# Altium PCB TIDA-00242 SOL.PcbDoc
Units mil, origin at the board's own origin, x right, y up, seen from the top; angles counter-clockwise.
Board outline 2500 x 1000 mil, 2 copper layers (Top Layer, Bottom Layer), stack 62 mil thick; 20 components, 6 nets, 29 pads, 0 vias.
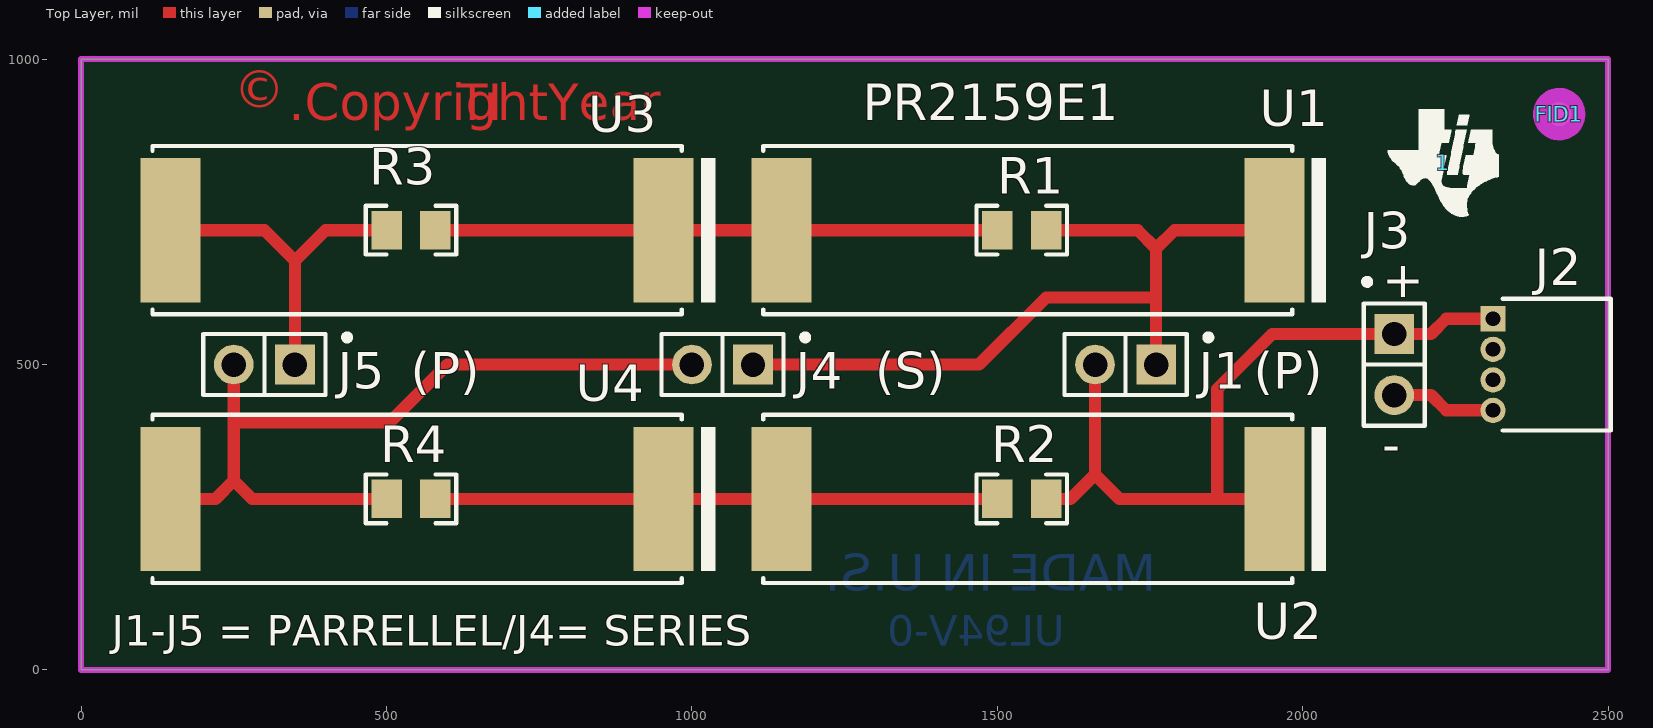
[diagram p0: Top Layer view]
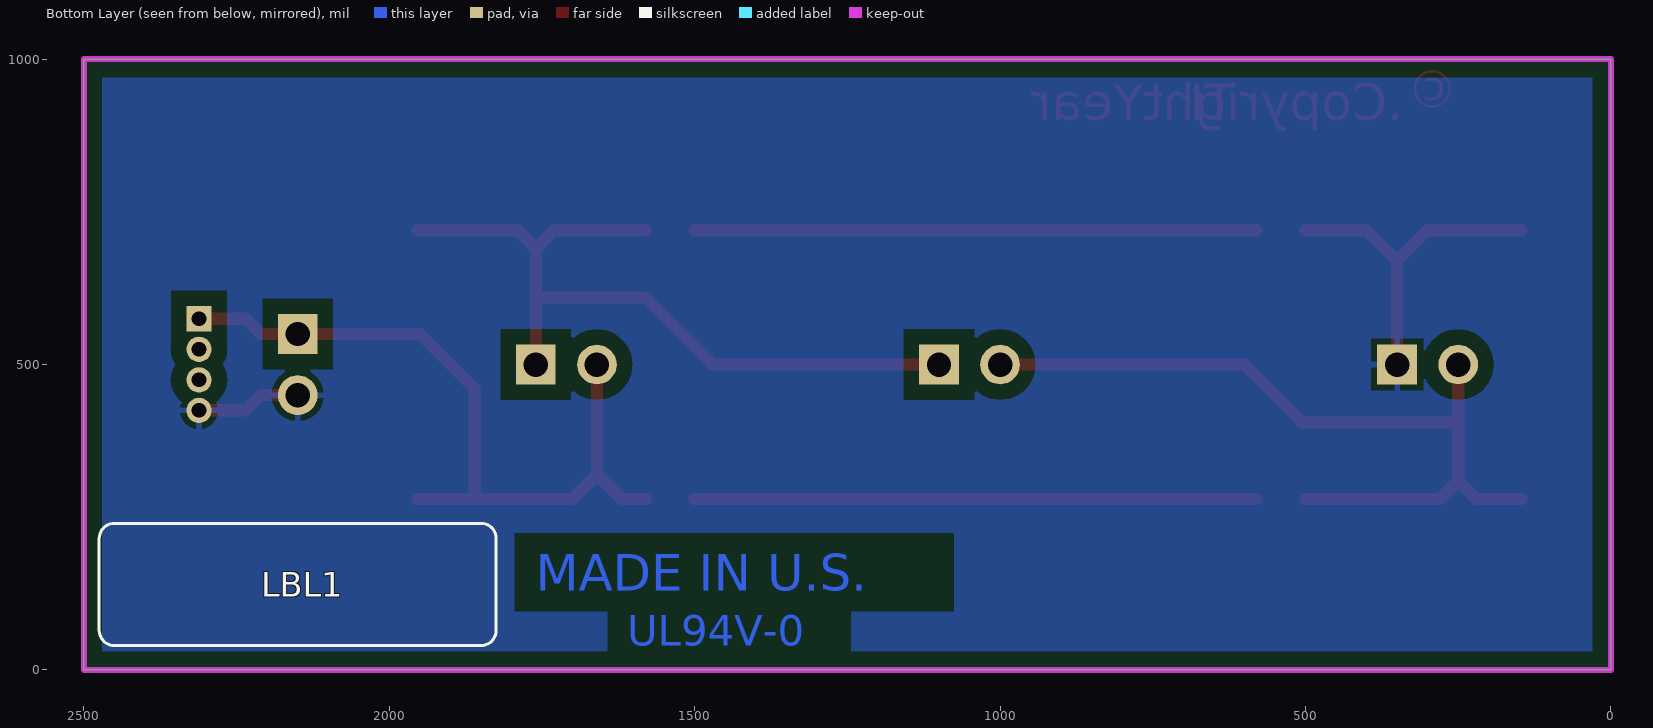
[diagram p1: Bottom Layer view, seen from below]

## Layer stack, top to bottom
Top Layer: signal copper 1.4
Dielectric: core 59.2, FR-4, Dk 4.8
Bottom Layer: signal copper 1.4

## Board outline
0,0 0,1000 2500,1000 2500,0 0,0

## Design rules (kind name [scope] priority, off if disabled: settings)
AcuteAngle [All] p1: minimum=4.50000000000000E+0001 checktracksonly=FALSE
AssemblyTestPointUsage [All] p1: valid=2
Clearance Clearance_BoardEdge_MountingHoles [OnCopper and InComponentClass('Mounting Holes') vs IsKeepOut] p1: gap=40
Clearance Clearance_BoardEdge_Poly [OnCopper and InPoly vs IsKeepOut] p2: gap=25
Clearance Clearance_BoardEdge [OnCopper and Not InComponentClass('Logo') and not InComponentClass('FiducialMark') and not InRegion(1000,500,4000,800) and Not IsKeepout vs IsKeepOut] p3: gap=75
Clearance Clearance_Poly [InPolygon] p4: gap=25
Clearance [All] p5: gap=8
ComponentClearance ComponentClearance_Logo [InComponentClass('Logo')] p1: gap=50 collisioncheckmode=3 verticalgap=10 showdistances=FALSE
ComponentClearance ComponentClearance_ScrewToNut [(HasFootprint('NY PMS 440 0025 PH')) vs (HasFootprint('Keystone_1902C'))] p2: gap=20 collisioncheckmode=3 verticalgap=10 showdistances=FALSE
ComponentClearance ComponentClearance_MountingHoles [InComponentClass('Mounting Holes')] p3: gap=20 collisioncheckmode=3 verticalgap=100000 showdistances=FALSE
ComponentClearance ComponentClearance_SmallPassives [HasFootprint('0201*') or HasFootprint('0402*') or HasFootprint('0508') or HasFootprint('0603*') or HasFootprint('0612') or HasFootprint('0805*') or HasFootprint('0815*') or HasFootprint('0830*') or HasFootprint('1206*') or HasFootprint('1210*') or HasFootprint('1808*') or HasFootprint('1812*') or HasFootprint('1825*') or HasFootprint('2010*') or HasFootprint('2220*') or HasFootprint('2225*') or HasFootprint('2512*') or HasFootprint('2728*') or HasFootprint('3518*') vs HasFootprint('0201*') or HasFootprint('0402*') or HasFootprint('0508') or HasFootprint('0603*') or HasFootprint('0612') or HasFootprint('0805*') or HasFootprint('0815*') or HasFootprint('0830*') or HasFootprint('1206*') or HasFootprint('1210*') or HasFootprint('1808*') or HasFootprint('1812*') or HasFootprint('1825*') or HasFootprint('2010*') or HasFootprint('2220*') or HasFootprint('2225*') or HasFootprint('2512*') or HasFootprint('2728*') or HasFootprint('3518*')] p4: gap=20 collisioncheckmode=3 verticalgap=10 showdistances=FALSE
ComponentClearance ComponentClearance_THtoSMT [IsThruComponent vs IsSMTComponent] p5: gap=20 collisioncheckmode=3 verticalgap=20 showdistances=FALSE
ComponentClearance ComponentClearance_THtoTH [IsThruComponent vs IsThruComponent] p6: gap=20 collisioncheckmode=3 verticalgap=20 showdistances=FALSE
ComponentClearance [All] p7: gap=20 collisioncheckmode=3 verticalgap=20 showdistances=FALSE
DiffPairsRouting [All] p1: maxlimit=100 minlimit=10 mostfreqgap=10 maxuncoupledlength=1000
FabricationTestPointUsage TestPointUsage [All] p1: valid=2 allowmultiple=FALSE
FabricationTestpoint Testpoint [All] p1: side=3 testpointundercomponent=TRUE minsize=40 maxsize=100 preferedsize=60 minholesize=0 maxholesize=40 preferedholesize=32 testpointgrid=1 allowsidetop=TRUE allowsidebottom=TRUE usegrid=TRUE gridtolerance=0.01
FanoutControl Fanout_LCC [IsLCC] p1: bgadir=Out bgaviamode=Centered fanoutstyle=Auto fanoutdirection=Alternating viagrid=1 // Fanout_LCC (Default Rule)
FanoutControl Fanout_BGA [IsBGA] p2: bgadir=Out bgaviamode=Centered fanoutstyle=Auto fanoutdirection=Alternating viagrid=1 // Fanout_BGA (Default Rule)
FanoutControl Fanout_Default [All] p4: bgadir=Out bgaviamode=Centered fanoutstyle=Auto fanoutdirection=Alternating viagrid=1 // Fanout_Default (Default Rule)
FanoutControl Fanout_Small [(CompPinCount < 5)] p5: bgadir=Out bgaviamode=Centered fanoutstyle=Auto fanoutdirection=OutThenIn viagrid=1 // Fanout_Small (Default Rule)
HoleSize [All] p1: absolutevalues=TRUE maxlimit=251 minlimit=8 maxpercent=80.000 minpercent=20.000
MinimumAnnularRing [All] p1: minimumring=9
MinimumSolderMaskSliver MinimumSolderMaskSliver_Logo [InComponentClass('Logo') vs InComponentClass('Logo')] p1: minsoldermaskwidth=0.7
MinimumSolderMaskSliver [All] p2: minsoldermaskwidth=4
PlaneConnect [All] p1: planeconnectstyle=Relief reliefexpansion=10 reliefentries=4 reliefconductorwidth=10 reliefairgap=10
PolygonConnect [All] p1: connectstyle=Relief reliefconductorwidth=10 reliefentries=4 polygonreliefangle="90 Angle" airgapwidth=10
RoutingVias [All] p1: holewidth=16 width=34 viastyle="Through Hole" minholewidth=8 minwidth=26 maxholewidth=40 maxwidth=65
SMDToCorner [All] p1: distance=30000
SilkToSilkClearance [All] p1: silktosilkclearance=5
SilkscreenOverComponentPads [All] p1: minsilkscreentomaskgap=5
SolderMaskExpansion [All] p1: expansion=3
Width [All] p1: maxlimit=100 minlimit=6 preferedwidth=10 checkconnectedcopper=TRUE
14 further rules are at their usual default settings.

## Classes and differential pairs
component class "PR2159 sheet 2": J1 J2 J3 J4 J5 R1 R2 R3 R4 U1 U2 U3 U4
component class Logo: ""
component class "PR2159 sheet 3": FID1 LBL1 ZZ1 ZZ2 ZZ3 ZZ4 ""
component class FiducialMark: FID1
component class AssemblyNote: ZZ1 ZZ2 ZZ3 ZZ4
component class Label: LBL1

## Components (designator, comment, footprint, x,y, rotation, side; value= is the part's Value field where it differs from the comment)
1 "Texas Instruments" TI_Symbol_Overlay_Small 2230,830 r0 top
FID1 "Fiducial" Fiducial10-20 2420,910 r0 top
J1 "90120-0122" CONN_90120-0122 1710,500 r180 top
J2 "LPPB041NGCN-RC" Sullins_LPPB041NGCN 2410,500 r90 top
J3 "90120-0122" CONN_90120-0122 2150,500 r270 top
J4 "90120-0122" CONN_90120-0122 1050,500 r180 top
J5 "90120-0122" CONN_90120-0122 300,500 r180 top
LBL1 "Size: 0.65\" x 0.20 \"" Label_650x200 2150,140 r180 bottom
R1 "CRCW08050000Z0EA" 0805_HV 1540,720 r0 top
R2 "CRCW08050000Z0EA" 0805_HV 1540,280 r0 top
R3 "CRCW08050000Z0EA" 0805_HV 540,720 r0 top
R4 "CRCW08050000Z0EA" 0805_HV 540,280 r0 top
U1 "KXOB22-04X3L" KXOB22-04X3 1550,720 r180 top
U2 "KXOB22-04X3L" KXOB22-04X3 1550,280 r180 top
U3 "KXOB22-04X3L" KXOB22-04X3 550,720 r180 top
U4 "KXOB22-04X3L" KXOB22-04X3 550,280 r180 top
ZZ1 "This Assembly Note is for PCB labels only" AssemblyNoteLabel 185,3938 r0 top
ZZ2 "These assemblies are ESD sensitive, ESD precautions shall be observed." AssemblyNote 185,3829.11 r0 top
ZZ3 "These assemblies must be clean and free from flux and all contaminants. Use of no clean flux is not acceptable." AssemblyNote 185,3740.56 r0 top
ZZ4 "These assemblies must comply with workmanship standards IPC-A-610 Class 2., unless otherwise specified." AssemblyNote 185,3652 r0 top

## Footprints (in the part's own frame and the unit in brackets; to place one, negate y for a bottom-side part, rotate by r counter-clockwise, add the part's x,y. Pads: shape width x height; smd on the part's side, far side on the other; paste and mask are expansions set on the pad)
0805_HV [mil] "0805 with 30mil clearance between pads"
  rect 50x63 smd: 1(-40,0) 2(40,0)
  silkscreen extent -74,-40 74,40, body extent -43,-29 43,29, height 43
AssemblyNote [mil] "Assembly Note"
AssemblyNoteLabel [mil] "Assembly Note for PCB Labels"
CONN_90120-0122 [mm] "Molex"
  rect 1.65x1.65 hole 1.016 mask+0: 1(-1.27,0)
  round 1.65 hole 1.016 mask+0: 2(1.27,0)
  silkscreen extent -3.57,-1.27 2.54,1.27, body extent -2.54,-1.27 2.54,1.27, height 9.29
Fiducial10-20 [mm]
  round 1 smd paste-0.5 mask+0.5: 1(0,0)
  Top Layer keep-out circle w1.178: c0,0 r0.5
KXOB22-04X3 [mm] "IXYS"
  rect 2.5x6 smd: 1(-10.25,0) 2(10.25,0)
  silkscreen extent -12.4,-3.5 11,3.5, body extent -11,-3.5 11,3.5, height 1.81
Label_650x200 [mil] "Thermal Transfer Label"
  silkscreen extent -325,-100 325,100, body extent -326,-101 326,101, height 1
Sullins_LPPB041NGCN [mm] "Sullins"
  rect 1.05x1.05 hole 0.61 mask+0.05: 1(1.905,2.5)
  round 1.05 hole 0.61 mask+0.05: 2(0.635,2.5) 3(-0.635,2.5) 4(-1.905,2.5)
  silkscreen extent -2.74,-2.4 2.74,2.1, body extent -2.74,-2.4 2.74,2.58, height 2.22
TI_Symbol_Overlay_Small [mil]
  silkscreen extent -90,-88 91,88

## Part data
1: library part TI_Logo, "Texas Instrument Corporate Signature"
FID1: "Fiducial mark.  There is nothing to buy or mount."
J1 J3 J4 J5: "Header, 100mil, 2x1, Tin plated, TH"
J2: "Receptacle, 50mil, 4x1, R/A, TH"
LBL1: library part THT-14-423-10, "Thermal Transfer Printable Labels, 0.650\" W x 0.200\" H - 10,000 per roll"
R1 R2 R3 R4: "RES, 0 ohm, 5%, 0.125W, 0805"
U1 U2 U3 U4: "MONOCRYSTALLINE SOLAR CELL, 22MM X 7MM, SMD"
ZZ1: library part AssemblyNoteLabel
ZZ2 ZZ3 ZZ4: library part AssemblyNote

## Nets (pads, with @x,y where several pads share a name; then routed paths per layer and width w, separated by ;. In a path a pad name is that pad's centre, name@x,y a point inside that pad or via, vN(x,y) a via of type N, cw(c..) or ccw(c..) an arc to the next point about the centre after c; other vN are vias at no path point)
GND: J2.4 J3.2 J5.1 R3.1 U3.2 | length 736.9
  Top Layer w20: U3.2 300,720 350,670 ; J5.1 350,670 ; R3.1 400,720 350,670 ; J3.2 2210,450 2235,425 J2.4
NetJ1_1: J1.1 J4.1 R1.2 U1.1 | length 1294
  Top Layer w20: J4.1 1470,500 1580,610 1760,610 ; R1.2 1730,720 1760,690 ; J1.1 1760,610 ; U1.1 1790,720 1760,690 ; 1760,610 1760,690
NetJ1_2: J1.2 J2.1 J3.1 R2.2 U2.1 | length 1265.9
  Top Layer w20: R2.2 1620,280 1660,320 ; J1.2 1660,320 ; U2.1 1860,280 ; J2.1 2235,575 2210,550 J3.1 1950,550 1860,460 1860,280 ; 1660,320 1700,280 1860,280
NetJ4_2: J4.2 J5.2 R4.1 U4.2 | length 1357.7
  Top Layer w20: U4.2 220,280 250,310 ; J5.2 250,405 ; R4.1 280,280 250,310 ; J4.2 600,500 505,405 250,405 ; 250,310 250,405
NetR1_1: R1.1 R3.2 U1.2 U3.1 | length 920
  Top Layer w20: R3.2 U3.1 U1.2 R1.1
NetR2_1: R2.1 R4.2 U2.2 U4.1 | length 920
  Top Layer w20: R4.2 U4.1 U2.2 R2.1
pads on no net: FID1.1 J2.2 J2.3

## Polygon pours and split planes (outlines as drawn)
GND on Bottom Layer "Bottom Layer-No Net" (solid, remove dead copper, pour order 4): 0,0 0,1000 2500,1000 2500,0 0,0

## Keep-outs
Keep-Out Layer:
  lines w10: 4950,-5 ccw(c4950,0) 4955,0 ; 4950,-5 ccw(c4950,0) 4955,0 ; 4950,-5 ccw(c4950,0) 4955,0 ; 4950,-5 ccw(c4950,0) 4955,0 ; 4950,-5 ccw(c4950,0) 4955,0 ; 4950,-5 ccw(c4950,0) 4955,0 ; 4950,3455 cw(c4950,3450) 4955,3450 ; 4950,3455 cw(c4950,3450) 4955,3450 ; 4950,3455 cw(c4950,3450) 4955,3450 ; 4950,3455 cw(c4950,3450) 4955,3450 ; 4950,3455 cw(c4950,3450) 4955,3450 ; 4950,3455 cw(c4950,3450) 4955,3450 ; 0,0 2500,0 2500,1000 0,1000 0,0
  text ".Layer_Name" at 577,-858.49 h60

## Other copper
Top Layer:
  text "©" at 250,900 h105
  text ".CopyrightYear" at 340,900 h60
  text "TI" at 616,900 h60
  text ".Layer_Name" at 577,-858.49 h60
Bottom Layer:
  text ".VersionControl_RevNumber" at 3891,179.5 h60
  text "SVN:" at 4170,179.5 h60
  text "MADE IN U.S." at 1760,130 h60
  text "UL94V-0" at 1610,40 h50
  text ".Layer_Name" at 577,-858.49 h60

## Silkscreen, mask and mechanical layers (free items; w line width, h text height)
Top Overlay:
  text "PR2159E1" at 1280,900 h60
  text "+" at 2130,610 h60
  text "(P)" at 540,460 h60
  text "(S)" at 1300,460 h60
  text "(P)" at 1920,460 h60
  text "-" at 2130,340 h60
  text "J1-J5 = PARRELLEL/J4= SERIES" at 50,40 h50
  text ".Layer_Name" at 577,-858.49 h60
Bottom Overlay:
  text ".Layer_Name" at 577,-858.49 h60
Top Paste:
  text ".Layer_Name" at 577,-858.49 h60
Bottom Paste:
  text ".Layer_Name" at 577,-858.49 h60
Top Solder:
  text ".Layer_Name" at 577,-858.49 h60
  text ".Layer_Name" at 577,-858.49 h60
Bottom Solder:
  text ".Layer_Name" at 577,-858.49 h60
Drill Guide:
  text ".Layer_Name" at 577,-858.49 h60
M1 Board Outline:
  lines w10: 750,1000 0,1000 ; 0,1000 0,0 2500,0 2500,1000 0,1000
  text ".Layer_Name" at 577,-858.49 h60
M2 Board Dimensions:
  rectangle: -0.5,-285.5 124.5,-160.5
  rectangle: 124.5,-410.5 499.5,-285.5
  lines w7: -0.5,-285.5 999.5,-285.5 ; 124.5,-410.5 124.5,-160.5 ; 249.5,-410.5 249.5,-160.5 ; 499.5,-410.5 499.5,-160.5 ; 749.5,-410.5 749.5,-160.5 ; -0.5,-410.5 999.5,-410.5 999.5,-160.5 -0.5,-160.5 -0.5,-410.5
  lines w10: -0.5,-475.5 -0.5,-455.5 ; 59.5,-485.5 -0.5,-465.5 ; 59.5,-445.5 -0.5,-465.5 ; 223.58,-465.5 -0.5,-465.5 ; 775.42,-465.5 999.5,-465.5 ; 939.5,-485.5 999.5,-465.5 ; 939.5,-445.5 999.5,-465.5 ; 999.5,-475.5 999.5,-455.5
  text "1000 (mil)" at 233.58,-501.49 h60
  text ".Layer_Name" at 577,-858.49 h60
M3 3D STEP Top:
  text ".Layer_Name" at 577,-858.49 h60
M4 3D STEP Bottom:
  text ".Layer_Name" at 577,-858.49 h60
M5 Assembly Top:
  lines w7: 5139,110.5 6264,110.5 ; 5139,233 6261.5,233 ; 5454,-9.5 5454,353 ; 5839,-9.5 5139,-9.5 ; 5839,353 5139,353 ; 5139,-9.5 6264,-9.5 6264,353 5139,353 ; 5139,-9.5 5139,353
  lines w10: -292,-930.17 6308,-930.17 ; -292,-726.83 6310,-726.83 ; -292,-523.5 -292,-1133.5 3713,-1133.5 6310,-1133.5 6310,-523.5 -291.5,-523.5 -291.5,-1133.5 1284,-1133.5 ; 2173,-1133.5 2173,-523.5 ; 3440,-726.83 3440,-523.5 ; 4280,-726.83 4280,-523.5 ; 4902,-1140 4902,-937.17
  text "TABLE 1" at 5526.5,388 h40
  text "Variant" at 5164,278 h40
  text "Label text" at 5599,278 h40
  text "001" at 5231.5,158 h40
  text "ChangeMe!" at 5509,155.5 h40
  text "002" at 5231.5,33 h40
  text "ChangeMe!" at 5504,30.5 h40
  text "COMPONENTS MARKED 'DNP' SHOULD NOT BE POPULATED." at 1153.5,-318.5 h60
  text "ASSEMBLY VARIANT:" at 1153,-434 h60
  text ".VariantName" at 2189,-434 h60
  text "PCB VIEWED FROM TOP SIDE" at -228.5,-655.67 h60
  text "BOARD #:" at 2248,-655.67 h60
  text ".PRJ_Number" at 2793.5,-655.67 h60
  text "REV:" at 3638,-655.67 h60
  text ".PCB_Rev" at 3929.5,-655.67 h60
  text "SVN REV:" at 4476,-655.67 h60
  text ".VersionControl_RevNumber" at 4982,-655.67 h60
  text "IGNORE ->" at -228.5,-858.49 h60
  text "PLOT NAME =" at -228.5,-1064.34 h60
  text ".plot_File_Name" at 577,-1064.34 h60
  text "GENERATED    :" at 2250,-1064.34 h60
  text ".Print_Date" at 3119.5,-1064.34 h60
  text ".Print_Time" at 3848.5,-1064.34 h60
  text "TEXAS INSTRUMENTS" at 5113,-1064.34 h60
M6 Assembly Bottom:
  lines w10: -292.5,-727.33 6309.5,-727.33 ; -290.5,-930.67 6309.5,-930.67 ; 1115.5,-1140.5 1115.5,-937.67 ; 1737.5,-727.33 1737.5,-524 ; 2577.5,-727.33 2577.5,-524 ; 3844.5,-1134 3844.5,-524 ; 4733.5,-1134 6309,-1134 6309,-524 -292.5,-524 -292.5,-1134 2304.5,-1134 6309.5,-1134 6309.5,-524
  text "COMPONENTS MARKED 'DNP' SHOULD NOT BE POPULATED." at 6102,-318 h60
  text ".VariantName" at 5058,-434 h60
  text "ASSEMBLY VARIANT:" at 6097,-434 h60
  text ".VersionControl_RevNumber" at 1035.5,-656.17 h60
  text "SVN REV:" at 1541.5,-656.17 h60
  text ".PCB_Rev" at 2088,-656.17 h60
  text "REV:" at 2379.5,-656.17 h60
  text ".PRJ_Number" at 3224,-656.17 h60
  text "BOARD #:" at 3769.5,-656.17 h60
  text "PCB VIEWED FROM BOTTOM SIDE" at 6246,-656.17 h60
  text "IGNORE ->" at 2547.85,-858.49 h60
  text "TEXAS INSTRUMENTS" at 904.5,-1064.84 h60
  text ".Print_Time" at 2169,-1064.84 h60
  text ".Print_Date" at 2898,-1064.84 h60
  text "GENERATED    :" at 3767.5,-1064.84 h60
  text ".plot_File_Name" at 5440.5,-1064.84 h60
  text "PLOT NAME =" at 6246,-1064.84 h60
M9 Title Sheet:
  drawing of 57 lines, arcs and shapes, not listed
  text "1" at 739.84,8036.5 h70
  text "2" at 3235.5,8036.5 h70
  text "3" at 5724.84,8036.5 h70
  text "4" at 8231.51,8036.5 h70
  text "5" at 10730.5,8036.5 h70
  text "6" at 13235.5,8036.5 h70
  text "A" at -416.5,6893.5 h70
  text "A" at 14383.5,6893.5 h70
  text "B" at -416.5,4513.5 h70
  text "B" at 14383.5,4513.5 h70
  text "C" at -416.5,2138.5 h70
  text "C" at 14383.5,2138.5 h70
  text "PROJECT TITLE:" at 11343.5,277.5 h45
  text ".PRJ_Title" at 11393.5,144.17 h70
  text "DESIGNED FOR:" at 11343.5,-23.5 h45
  text ".PRJ_Customer" at 11393.5,-163.5 h70
  text "D" at -416.5,-231.5 h70
  text "D" at 14383.5,-231.5 h70
  text "FILE NAME:" at 11343.5,-323.5 h45
  text ".PCB_File_Name_No_Path" at 11393.5,-443.5 h70
  text "Texas Instruments (TI) and/or its licensors do not warrant the accuracy or completeness of this specification" at 6374,-605.34 h45
  text "ENGINEER:" at 11343.5,-613.5 h45
  text "LAYOUT BY:" at 12848.5,-613.5 h45
  text "or any information contained therein. TI and/or its licensors do not warrant that this design will meet" at 6329.01,-718 h45
  text ".PRJ_Engineer" at 11393.5,-768.49 h70
  text ".PCB_Layout" at 12899,-768.49 h70
  text "the specifications, will be suitable for your application or fit for any particular purpose, or will operate in" at 6329.01,-830.67 h45
  text ".Layer_Name" at 577,-858.49 h60
  text "ALTIUM DESIGNER VERSION:" at 12848.5,-923.5 h45
  text "an implementation. TI and/or its licensors do not warrant that the design is production worthy. You should" at 6329.01,-943.33 h45
  text "completely validate and test your design implementation to confirm the system functionality for your application." at 6374,-1056 h45
  text ".print_Scale" at 11393.5,-1056.83 h70
  text ".Application_BuildNumber" at 12899,-1056.83 h70
  text "1" at 739.84,-1263.5 h70
  text "2" at 3235.5,-1263.5 h70
  text "3" at 5724.84,-1263.5 h70
  text "4" at 8231.51,-1263.5 h70
  text "5" at 10730.5,-1263.5 h70
  text "6" at 13235.5,-1263.5 h70
M10 Fab Notes:
  drawing of 212 lines, arcs and shapes, not listed
  text "DESIGN INFORMATION" at 12381.02,6810 h60
  text "(REFER ALSO ARRAY/PANEL PROFILING INFORMATION)" at 12019.46,6648.29 h60
  text "BOARD SIZE" at 11333.46,6644 h60
  text "1000MIL" at 11795.78,6516.18 h60
  text "X" at 12301.46,6516.18 h60
  text "800MIL" at 12532.78,6516.18 h60
  text "Number of Layers :" at 11736.46,6319 h60
  text "2" at 12831.27,6309 h60
  text "MIN. TRACK WIDTH:" at 11736.46,6180 h60
  text "8" at 12832.7,6180 h60
  text "MIL" at 12987.46,6180 h60
  text "MIN. CLEARANCE:" at 11736.46,6048 h60
  text "8" at 12832.7,6048 h60
  text "MIL" at 12987.46,6048 h60
  text "MIN. VIA PAD SIZE:" at 11736.46,5916 h60
  text "24" at 12802.71,5916 h60
  text "MIL" at 12987.46,5916 h60
  text "0.05mm (2MIL)" at 12431.46,5774.29 h60
  text "MINIMUM ANNULAR RING" at 11407.23,5770 h60
  text "EXTERNAL" at 13139.46,5770 h60
  text "PER" at 11607.23,5652 h60
  text "IPC-D-275 CLASS 2 LEVEL C" at 11827.23,5652 h60
  text "MIL, HOLES" at 13315.46,5539.71 h60
  text "+/-" at 12923,5539 h60
  text "+/-" at 13777,5539 h60
  text "REGISTRATION TOLERANCES:" at 11407.23,5534 h60
  text "METAL" at 12607,5534 h60
  text "5" at 13183.2,5534 h60
  text "3" at 14016.2,5534 h60
  text "MIL" at 14132.46,5534 h60
  text "MATERIAL:" at 11332.46,5324.54 h60
  text "FR-4 High Tg" at 12318.9,5184.21 h60
  text "FR-408" at 11753.46,5175.64 h60
  text "X" at 12165.46,5175.64 h60
  text "OTHER" at 13241.46,5175.64 h60
  text "62 MIL (1.6mm) +/-10%" at 12073.56,5012.92 h60
  text "THICKNESS:" at 11407.23,5008.64 h60
  text "OTHER" at 13358.46,5008.64 h60
  text "38MIL" at 13758.46,5008.64 h60
  text "X" at 13230,5000 h60
  text "TOLERANCE:" at 11407.23,4850.64 h60
  text "X" at 12246.53,4850.64 h60
  text "ANSI IPC-6012 TYPE 3 CLASS 2" at 12433.48,4850.64 h60
  text "OTHER +/-" at 12433.46,4694.64 h60
  text "BOW & TWIST:" at 11407.23,4537.64 h60
  text "X" at 12246.53,4537.64 h60
  text "ANSI IPC-6012 TYPE 3 CLASS 2" at 12433.48,4537.64 h60
  text "OTHER +/-" at 12433.46,4379.13 h60
  text "COPPER THICKNESS (FINISHED):" at 11332.46,4243.64 h60
  text "1.4MIL (1oz)" at 12212.46,4090.92 h60
  text "2MIL (1.4oz)" at 12979.46,4090.92 h60
  text "2.8MIL (2oz)" at 13706.46,4090.92 h60
  text "OUTER:" at 11689.46,4086.64 h60
  text "X" at 12084,4086 h60
  text "1.4MIL (1oz)" at 12212.46,3933.92 h60
  text "2.8MIL (2oz)" at 12979.46,3933.92 h60
  text "N/A" at 13706,3934.29 h60
  text "INNER SIGNAL:" at 11400.38,3929.64 h60
  text "X" at 12085.42,3929.64 h60
  text "DRILLING:" at 11332.46,3790.64 h60
  text "REFERENCE:" at 11407.23,3673.64 h60
  text "X" at 12055.46,3673.64 h60
  text "AS SHOWN" at 12242.46,3673.64 h60
  text "X" at 12956.46,3673.64 h60
  text "NC_DRILL FILES" at 13093.46,3673.64 h60
  text "PTH MIN COPPER THICKNESS:" at 11407.23,3515.64 h60
  text "X" at 12757.46,3515.64 h60
  text "1MIL" at 12894.46,3515.64 h60
  text "OTHER" at 13391.46,3515.64 h60
  text "BOARD FINISH:" at 11332.46,3356.64 h60
  text "SILKSCREEN:" at 11487.68,3238.64 h60
  text "X" at 12436.46,3238.64 h60
  text "TOP" at 12562.46,3238.64 h60
  text "X" at 12946.46,3238.64 h60
  text "BOTTOM" at 13073.46,3238.64 h60
  text "SILKSCREEN COLOR:" at 11487.68,3071.64 h60
  text "X" at 12435.42,3071.64 h60
  text "WHITE" at 12562.46,3071.64 h60
  text "OTHER" at 13073.46,3071.64 h60
  text "SOLDER RESIST COLOR:" at 11487.68,2901.64 h60
  text "X" at 12055.42,2742.44 h60
  text "GREEN" at 12182.46,2742.44 h60
  text "BLUE" at 12773.46,2742.44 h60
  text "OTHER" at 13311.46,2742.44 h60
  text "IMMERSION GOLD (ENIG)" at 12393.46,2553.92 h60
  text "ENEPIG" at 13731,2550.64 h60
  text "SURFACE FINISH:" at 11332.46,2549.64 h60
  text "X" at 12206.51,2549.64 h60
  text "IMM. TIN/SILVER OR EQUIV" at 11662,2392.64 h60
  text "OTHER" at 13093.46,2392.64 h60
  text "X" at 12210,2220 h60
  text "ARRAY/PANEL:" at 11332.46,2213.64 h60
  text "CUT AND TRIM PER MECH LAYER 1" at 12393.46,2209.35 h60
  text "N.C. ROUTE" at 12393.46,2057.64 h60
  text "V. SCORE" at 13259.46,2057.64 h60
  text "CERTIFICATION:" at 11332.46,1920.64 h60
  text "MATERIALS AND WORKMANSHIP FOR ALL PCBS" at 12057.46,1920.64 h60
  text "TO MEET OR EXCEED THE REQUIREMENTS OF:" at 12057.46,1822.64 h60
  text "X" at 11683.96,1686.13 h60
  text "ANSI IPC-A-600F CLASS ->" at 11822.96,1686.13 h60
  text "X" at 13462.02,1686.13 h60
  text "2" at 13580.96,1686.14 h60
  text "1" at 13265.96,1684.64 h60
  text "3" at 13934.96,1684.64 h60
  text "X" at 11686.02,1526.64 h60
  text "UL 94V-0" at 11822.96,1526.64 h60
  text "X" at 12498.02,1526.64 h60
  text "RoHS" at 12634.96,1526.64 h60
  text "OTHER" at 13279.36,1526.64 h60
  text "PER ORDER" at 13676.42,1526.64 h60
  text "ADDITIONAL REQUIREMENTS:" at 11332.46,1385.64 h60
  text "MICROSECTION:" at 11407.23,1270.64 h60
  text "YES" at 12312.96,1270.64 h60
  text "REQUIRED" at 13174.46,1114.49 h60
  text "BARE BOARD ELEC. TEST:" at 11407.23,1111.64 h60
  text "NONE" at 12712.96,1111.64 h60
  text "X" at 13047.46,1111.64 h60
  text "PER ORDER" at 13766.46,1111.64 h60
  text "MANUFACTURER'S UL:" at 11407.23,954.64 h60
  text "RAIL" at 12572.96,950.35 h60
  text "METAL" at 13064.77,950.35 h60
  text "X" at 13440,950 h60
  text "SILK" at 13576.46,950.35 h60
  text ".Layer_Name" at 577,-858.49 h60
M11 Gerber Information:
  lines w10: -292,-930.17 6308,-930.17 ; -292,-726.83 6310,-726.83 ; -292,-523.5 -292,-1133.5 3713,-1133.5 6310,-1133.5 6310,-523.5 -291.5,-523.5 -291.5,-1133.5 1284,-1133.5 ; 2173,-1133.5 2173,-523.5 ; 3440,-726.83 3440,-523.5 ; 4280,-726.83 4280,-523.5 ; 4902,-1140 4902,-937.17
  text "ALL ARTWORK VIEWED FROM TOP SIDE" at -228.5,-655.67 h60
  text "BOARD #:" at 2248,-655.67 h60
  text ".PRJ_Number" at 2793.5,-655.67 h60
  text "REV:" at 3638,-655.67 h60
  text ".PCB_Rev" at 3929.5,-655.67 h60
  text "SVN REV:" at 4476,-655.67 h60
  text ".VersionControl_RevNumber" at 4982,-655.67 h60
  text "LAYER NAME =" at -228.5,-858.49 h60
  text "PLOT NAME =" at -228.5,-1064.34 h60
  text ".plot_File_Name" at 577,-1064.34 h60
  text "GENERATED    :" at 2250,-1064.34 h60
  text ".Print_Date" at 3119.5,-1064.34 h60
  text ".Print_Time" at 3848.5,-1064.34 h60
  text "TEXAS INSTRUMENTS" at 5113,-1064.34 h60
M12 Stackup:
  lines w6: 11360,7460 13910,7460 ; 11360,7564.4 13910,7564.4 ; 11300,6975 ccw(c11334,6975) 11334,6941 13936,6941 ccw(c13936,6975) 13970,6975 13970,7681 ccw(c13936,7681) 13936,7715 11334,7715 ccw(c11334,7681) 11300,7681 11300,6975
  text "The Stackup Legend below this is static." at 11605.5,7874.5 h60
  text "If you change the stackup, update the Legend." at 11615.5,7784.5 h60
  text "Layer Stack Up Detail for: Ref_Design.PcbDoc" at 11360,7597.1 h57
  text "Layer" at 11360,7525.4 h24
  text "Gerber" at 12255.81,7525.4 h24
  text "Copper" at 12819.33,7525.4 h24
  text "Dielectric" at 13422.04,7525.4 h24
  text "Name" at 11360,7477.4 h24
  text "Document" at 12255.81,7477.4 h24
  text "Thickness" at 12819.33,7477.4 h24
  text "Material" at 13422.04,7477.4 h24
  text "Top Solder Mask" at 11360,7384.44 h34
  text "(.GTS)" at 12255.81,7384.44 h34
  text "Solder Resist" at 13422.04,7384.44 h34
  text "Top Layer" at 11360,7287.69 h34
  text "(.GTL)" at 12255.81,7287.69 h34
  text "1.4mil" at 12819.33,7287.69 h34
  text "FR-4" at 13422.04,7239.31 h34
  text "Bottom Layer" at 11360,7190.94 h34
  text "(.GBL)" at 12255.81,7190.94 h34
  text "1.4mil" at 12819.33,7190.94 h34
  text "Bottom Solder Mask" at 11360,7094.19 h34
  text "(.GBS)" at 12255.81,7094.19 h34
  text "Solder Resist" at 13422.04,7094.19 h34
  text ".Layer_Name" at 577,-858.49 h60
M13 Component Bodies Top:
  text ".Layer_Name" at 577,-858.49 h60
M14 Component Bodies Bottom:
  text ".Layer_Name" at 577,-858.49 h60
M15 Courtyards Top:
  text ".Layer_Name" at 577,-858.49 h60
M16 Courtyards Bottom:
  text ".Layer_Name" at 577,-858.49 h60
Drill Drawing:
  text ".legend" at 5122.5,725.5 h60
  text "Drill Table" at 5147.5,540.5 h60
  text ".Layer_Name" at 577,-858.49 h60

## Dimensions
0,0 to 0,1000 on M2 Board Dimensions
0,0 to 2500,0 on M2 Board Dimensions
